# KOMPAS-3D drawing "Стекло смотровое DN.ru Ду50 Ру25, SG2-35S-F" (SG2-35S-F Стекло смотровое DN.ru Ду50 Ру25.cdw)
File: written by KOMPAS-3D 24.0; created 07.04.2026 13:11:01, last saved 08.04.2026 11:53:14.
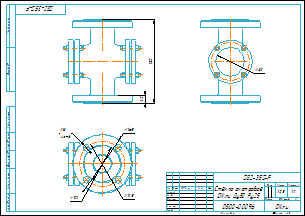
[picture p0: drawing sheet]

Document properties: Автор: Main; Форматы листов документа: A4; Полное имя файла: SG2-35S-F Стекло смотровое DN.ru Ду50 Ру25.m3d; Масса: 10.5; Наименование: Стекло смотровое DN.ru Ду50 Ру25; Количество листов документа: 1; Примечание: D500-00096

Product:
- Body: Тело 1  | qty 1
    Масса: 11.518228
- Part/product: Стекло смотровое DN.ru Ду50 Ру25  | designation SG2-35S-F
    Масса: 10.5
    Раздел спецификации: Прочие изделия
    Форматы листов документа: A4
    Примечание: D500-00096

Views: Вид 1, Снизу, Проекционный вид 2
Referenced files in D:\DN.ru Аутсерс\Стекло смотровое DN.ru\Стекло смотровое DN.ru SG2-34G-F тип В ГОСТ 21836-2021 Ду100 Ру16, углеродистая сталь, фланцевое\: SG2-34G-F тип В Стекло смотровое DN.ru Ду100 Ру16.m3d, SG2-34G-F тип ВСтекло смотровое DN.ru Ду100 Ру16.cdw
Referenced files in D:\DN.ru Аутсерс\Стекло смотровое DN.ru\SG2-35S-F Стекло смотровое DN.ru Ду50 Ру25\: SG2-35S-F Стекло смотровое DN.ru Ду50 Ру25.m3d
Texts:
  SG2-35S-F
  Стекло смотровое
  DN.ru Ду50 Ру25
  Стекло смотровое DN.ru Ду50 Ру25
  SG2-35S-F Стекло смотровое DN.ru Ду50 Ру25
Dimensions and other numbers on the sheet: 0; 3; 2; 4; 230; 20; 18; 4 отв.; 165; 102; 125; 1:2; 1; 10,5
